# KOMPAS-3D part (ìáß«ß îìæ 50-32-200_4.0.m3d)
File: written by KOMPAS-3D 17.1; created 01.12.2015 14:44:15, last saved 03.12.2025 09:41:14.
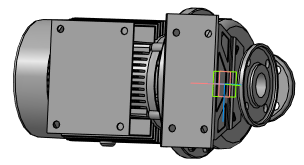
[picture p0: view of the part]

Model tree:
1. Операция без истории:3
